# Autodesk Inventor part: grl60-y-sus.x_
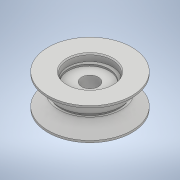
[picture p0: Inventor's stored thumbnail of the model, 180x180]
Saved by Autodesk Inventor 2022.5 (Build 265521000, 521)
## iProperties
Created: 2020-01
Part Number: grl60-y-sus.x_
Material: 一般
Document SubType Name: Modeling
Designer: ImaoCorp
Density: 1 g/cm^3
Appearance: 既定
Sending System: SOLIDWORKS 2018-2018316
MC: AMD64
MC_MODEL: Intel64 Family 6 Model 60 Stepping 3, GenuineIntel
OS: Windows_NT
FRU: Parasolid Version 30.0, build 310,  6- 8-2018
FORMAT: text
GUISE: transmit
KEY: grl60-y-sus
FILE: grl60-y-sus.x_t
DATE: Thu Jan 23 16:41:35 2020
Author: ImaoCorp
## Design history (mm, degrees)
feature "Base1"
node "ソリッド1"
